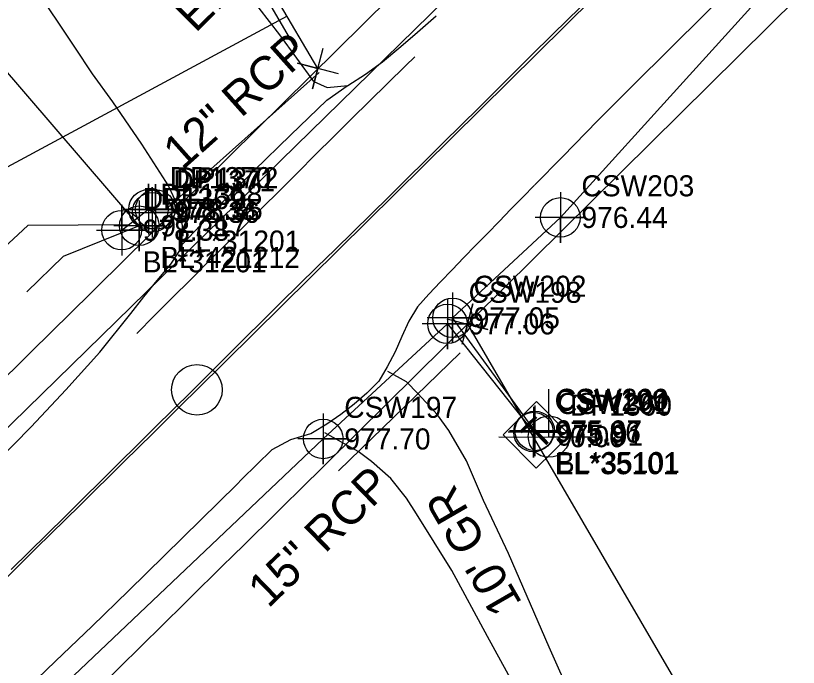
# Model space of a CAD drawing. Extents: x 1182322 to 1186765, y 572295 to 575411.
# Drawn here: x 1185253 to 1185345.8, y 574843 to 574920.3 of the extents above; entities that cross this region are included whole.
import ezdxf

# ---------------------------------------------------------------- set-up
doc = ezdxf.new("R2010")
doc.units = 0
for name, color, linetype in [('COGO Default Chain', 7, 'Continuous'), ('Exist Horizontal Alignment', 7, 'Continuous'), ('Exist Horizontal Alignment Point', 7, 'Continuous'), ('Exist Property Corner CELL', 7, 'Continuous'), ('Exist Property Iron Pin Text', 7, 'Continuous'), ('Exist Property Line', 7, 'Continuous'), ('Exist Property Line Leader', 7, 'Continuous'), ('Exist Right of Way Line', 7, 'Continuous'), ('Exist Roads EOP', 7, 'Continuous'), ('Exist Roads EOP Other', 7, 'Continuous'), ('Exist Roads EOT', 7, 'Continuous'), ('Exist Roads Soil', 7, 'Continuous'), ('Exist Roads Soil Text', 7, 'Continuous'), ('Exist Structure Minor Head and End Wall', 7, 'Continuous'), ('Exist Structure Minor Head and End Wall Cogo Comment', 7, 'Continuous'), ('Exist Structure Minor Head and End Wall Cogo Elevation', 7, 'Continuous'), ('Exist Structure Minor Head and End Wall Cogo Number', 7, 'Continuous'), ('Exist Structure Minor Head and End Wall Cogo Point CELL', 7, 'Continuous'), ('Exist Structure Minor Head and End Wall Leader', 7, 'Continuous'), ('Exist Structure Minor Pipes RCP 12 Inch', 7, 'Continuous'), ('Exist Structure Minor Pipes RCP 12 Inch Cogo Comment', 7, 'Continuous'), ('Exist Structure Minor Pipes RCP 12 Inch Cogo Number', 7, 'Continuous'), ('Exist Structure Minor Pipes RCP 12 Inch Cogo Point CELL', 7, 'Continuous'), ('Exist Structure Minor Pipes RCP 12 Inch Text', 7, 'Continuous'), ('Exist Structure Minor Pipes RCP 15 Inch', 7, 'Continuous'), ('Exist Structure Minor Pipes RCP 15 Inch Text', 7, 'Continuous'), ('Exist Structure Minor Pipes RCP 24 Inch Invert', 7, 'Continuous'), ('Exist Utilities Power Joint Use Telephone CELL', 7, 'Continuous'), ('Exist Utilities Power Joint Use Telephone Cogo Elevation', 7, 'Continuous'), ('Exist Utilities Power Joint Use Telephone Cogo Number', 7, 'Continuous'), ('Exist Utilities Telephone Pedestal CELL', 7, 'Continuous'), ('Exist Utilities Telephone Pedestal Cogo Elevation', 7, 'Continuous'), ('Exist Utilities Telephone Pedestal Cogo Number', 7, 'Continuous'), ('Exist Utilities Telephone UG Cable SUE LOS C', 7, 'Continuous'), ('Exist Utilities Telephone UG Cable SUE LOS C Cogo Comment', 7, 'Continuous'), ('Exist Utilities Telephone UG Cable SUE LOS C Cogo Elevation', 7, 'Continuous'), ('Exist Utilities Telephone UG Cable SUE LOS C Cogo Number', 7, 'Continuous'), ('Exist Utilities Telephone UG Cable SUE LOS C Cogo Point CELL', 7, 'Continuous'), ('Exist Utilities Water UG Line SUE LOS C', 7, 'Continuous')]:
    doc.layers.add(name, color=color, linetype=linetype)

msp = doc.modelspace()

# ---------------------------------------------------------------- linework, layer by layer
at = {"layer": 'COGO Default Chain'}
msp.add_line((1185274.486, 574875.929), (1185408.379, 575008.334), dxfattribs=at)
msp.add_arc((1175733.04, 584524.617), 13569.686, 314.0226276, 314.6798077, dxfattribs=at)
at = {"layer": 'Exist Horizontal Alignment'}
msp.add_line((1185274.486, 574875.929), (1185408.379, 575008.334), dxfattribs=at)
msp.add_arc((1175733.04, 584524.617), 13569.686, 314.0226276, 314.6798077, dxfattribs=at)
at = {"layer": 'Exist Horizontal Alignment Point'}
msp.add_circle((1185274.486, 574875.929), 3, dxfattribs=at)
at = {"layer": 'Exist Property Corner CELL'}
for p, q in [((1185288.832, 574914.024), (1185288.832, 574914.024)), ((1185306.543, 574883.722), (1185306.543, 574883.722))]:
    msp.add_line(p, q, dxfattribs=at)
for points in [[(1185291.252, 574913.394), (1185286.413, 574914.655), (1185288.832, 574914.024), (1185288.202, 574911.605), (1185289.463, 574916.443)], [(1185304.126, 574884.359), (1185308.961, 574883.084), (1185306.543, 574883.722), (1185307.181, 574886.139), (1185305.906, 574881.304)]]:
    msp.add_lwpolyline(points, dxfattribs=at)
at = {"layer": 'Exist Property Line'}
for p, q in [((1185288.832, 574914.024), (1185281.498, 574926.528)), ((1185306.543, 574883.722), (1185478.65, 574588.329))]:
    msp.add_line(p, q, dxfattribs=at)
at = {"layer": 'Exist Property Line Leader'}
msp.add_lwpolyline([(1185285.188, 574920.237), (1185235.405, 574893.412), (1185204.631, 574863.937)], dxfattribs=at)
at = {"layer": 'Exist Right of Way Line'}
for p, q in [((1185262.532, 574888.016), (1185396.426, 575020.422)), ((1185286.439, 574863.841), (1185420.333, 574996.246))]:
    msp.add_line(p, q, dxfattribs=at)
for radius, start in [(13552.686, 314.2300392), (13586.686, 314.1944782)]:
    msp.add_arc((1175733.04, 584524.617), radius, start, 314.6798077, dxfattribs=at)
at = {"layer": 'Exist Roads EOP'}
for points in [[(1185347.529, 574933.236), (1185343.278, 574929.003), (1185339.027, 574924.771), (1185334.768, 574920.546), (1185330.505, 574916.325), (1185326.242, 574912.105), (1185322.008, 574907.855), (1185317.807, 574903.573), (1185314.536, 574900.226)], [(1185288.36, 574912.51), (1185284.33, 574918.038), (1185280.656, 574922.818), (1185277.581, 574926.824)], [(1185288.363, 574912.507), (1185289.911, 574911.777), (1185292.376, 574912.012), (1185294.481, 574913.361), (1185296.497, 574914.837), (1185298.41, 574916.445), (1185300.312, 574918.068), (1185302.2, 574919.706), (1185302.862, 574920.289)], [(1185271.141, 574900.061), (1185270.086, 574901.734), (1185267.967, 574905.07), (1185264.519, 574910.077), (1185262.097, 574913.389)], [(1185272.771, 574893.19), (1185277.037, 574897.696), (1185281.274, 574901.942), (1185285.581, 574906.116), (1185289.899, 574910.281), (1185292.308, 574911.964)], [(1185266.661, 574884.989), (1185268.197, 574886.961), (1185269.785, 574888.89), (1185271.385, 574890.808), (1185272.746, 574892.9), (1185272.774, 574895.397), (1185272.188, 574897.827), (1185271.143, 574900.056)], [(1185314.503, 574900.193), (1185313.106, 574898.763), (1185311.709, 574897.333), (1185310.312, 574895.903), (1185308.914, 574894.473), (1185307.517, 574893.043), (1185306.128, 574891.605), (1185304.743, 574890.163), (1185303.361, 574888.719), (1185301.989, 574887.265), (1185300.646, 574885.784), (1185299.59, 574884.085), (1185298.787, 574882.261), (1185297.975, 574880.437), (1185297.044, 574878.669), (1185296.041, 574876.944), (1185294.627, 574875.529), (1185293.115, 574874.225), (1185291.535, 574873.002), (1185289.899, 574871.857), (1185288.196, 574870.811), (1185287.972, 574870.695)], [(1185224.719, 574842.308), (1185228.998, 574846.513), (1185233.316, 574850.678), (1185237.636, 574854.841), (1185241.957, 574859.003), (1185246.347, 574863.092), (1185250.631, 574867.291), (1185254.856, 574871.549), (1185258.96, 574875.924), (1185262.975, 574880.379), (1185266.642, 574884.965)], [(1185287.952, 574870.689), (1185285.568, 574870.011), (1185283.376, 574868.822), (1185281.598, 574867.065), (1185279.819, 574865.309), (1185279.215, 574864.713)], [(1185279.205, 574864.702), (1185274.932, 574860.49), (1185270.659, 574856.28), (1185266.367, 574852.088), (1185262.073, 574847.9), (1185257.739, 574843.744), (1185253.374, 574839.572), (1185249.07, 574835.458), (1185244.715, 574831.332), (1185240.395, 574827.17), (1185236.11, 574822.972), (1185231.831, 574818.769), (1185227.589, 574814.528), (1185223.349, 574810.285), (1185223.173, 574810.109)]]:
    msp.add_lwpolyline(points, dxfattribs=at)
at = {"layer": 'Exist Roads EOP Other'}
msp.add_lwpolyline([(1185262.097, 574913.389), (1185259.995, 574916.546), (1185250.077, 574931.376), (1185247.899, 574934.733), (1185245.446, 574937.892), (1185242.826, 574940.775), (1185237.847, 574945.524), (1185227.942, 574955.646), (1185217.22, 574966.654), (1185211.604, 574972.127), (1185207.269, 574976.346), (1185195.275, 574987.61), (1185178.895, 575002.931), (1185174.904, 575006.802), (1185172.104, 575009.848), (1185169.088, 575012.685), (1185149.972, 575030.515)], dxfattribs=at)
at = {"layer": 'Exist Roads EOT'}
for points in [[(1185320.734, 574922.076), (1185318.59, 574919.979), (1185316.451, 574917.877), (1185314.32, 574915.766), (1185312.191, 574913.652), (1185310.063, 574911.539), (1185307.934, 574909.426), (1185305.805, 574907.313), (1185303.677, 574905.2), (1185301.548, 574903.087), (1185299.418, 574900.975), (1185297.286, 574898.866), (1185295.147, 574896.763), (1185293.004, 574894.665), (1185290.862, 574892.565), (1185288.721, 574890.465), (1185286.58, 574888.365), (1185284.439, 574886.264), (1185282.302, 574884.16), (1185280.173, 574882.048), (1185278.047, 574879.933), (1185275.92, 574877.818), (1185273.792, 574875.704), (1185271.664, 574873.59), (1185269.536, 574871.476), (1185267.407, 574869.363), (1185265.277, 574867.251), (1185263.147, 574865.14), (1185261.015, 574863.029), (1185258.882, 574860.92), (1185256.748, 574858.813), (1185254.612, 574856.706), (1185252.476, 574854.6)], [(1185267.355, 574882.614), (1185269.477, 574884.734), (1185271.598, 574886.854), (1185273.718, 574888.975), (1185275.839, 574891.096), (1185277.959, 574893.217), (1185280.079, 574895.337), (1185282.2, 574897.458), (1185284.32, 574899.579), (1185286.44, 574901.7), (1185288.56, 574903.821), (1185290.688, 574905.934), (1185292.82, 574908.044), (1185294.951, 574910.155), (1185297.086, 574912.261), (1185299.225, 574914.363), (1185300.303, 574915.421)]]:
    msp.add_lwpolyline(points, dxfattribs=at)
at = {"layer": 'Exist Roads Soil'}
for points in [[(1185286.139, 574916.551), (1185280.456, 574926.323), (1185269.61, 574943.478), (1185250.019, 574976.538), (1185240.669, 574992.978), (1185236.689, 574996.97), (1185233.781, 575000.255), (1185231.347, 575003.099), (1185221.242, 575018.995), (1185207.439, 575010.283), (1185214.604, 574998.816), (1185215.218, 574997.747), (1185215.716, 574996.563), (1185216.433, 574994.858), (1185216.396, 574992.247), (1185215.47, 574988.497)], [(1185351.942, 574746.247), (1185352.472, 574749.736), (1185352.526, 574755.223), (1185351.823, 574762.645), (1185350.856, 574769.332), (1185349.342, 574775.949), (1185347.321, 574782.139), (1185344.159, 574788.72), (1185340.784, 574794.96), (1185335.757, 574804.276), (1185331.021, 574813.582), (1185326.994, 574821.946), (1185321.679, 574833.157), (1185316.254, 574845.408), (1185311.42, 574856.506), (1185308.478, 574862.796), (1185306.425, 574867.519), (1185304.367, 574871.088), (1185303.006, 574872.963), (1185300.672, 574875.507), (1185299.337, 574876.867), (1185297.137, 574878.078)], [(1185345.337, 574753.103), (1185345.588, 574758.315), (1185345.564, 574764.52), (1185344.547, 574771.506), (1185342.41, 574779.004), (1185338.522, 574788.293), (1185332.234, 574800.174), (1185324.951, 574815.353), (1185315.929, 574833.904), (1185308.943, 574846.652), (1185304.696, 574854.48), (1185300.528, 574861.225), (1185299.323, 574863.087), (1185297.465, 574865.42), (1185295.178, 574867.433), (1185293.604, 574868.601), (1185289.66, 574870.831)]]:
    msp.add_lwpolyline(points, dxfattribs=at)
at = {"layer": 'Exist Structure Minor Head and End Wall'}
msp.add_lwpolyline([(1185265.567, 574894.858), (1185268.749, 574897.338), (1185269.185, 574896.974), (1185269.561, 574897.314)], dxfattribs=at)
at = {"layer": 'Exist Structure Minor Head and End Wall Cogo Point CELL'}
for points in [[(1185265.749, 574897.338), (1185271.749, 574897.338), (1185268.749, 574897.338), (1185268.749, 574900.338), (1185268.749, 574894.338)], [(1185266.185, 574896.974), (1185272.185, 574896.974), (1185269.185, 574896.974), (1185269.185, 574899.974), (1185269.185, 574893.974)], [(1185266.561, 574897.314), (1185272.561, 574897.314), (1185269.561, 574897.314), (1185269.561, 574900.314), (1185269.561, 574894.314)], [(1185262.567, 574894.858), (1185268.567, 574894.858), (1185265.567, 574894.858), (1185265.567, 574897.858), (1185265.567, 574891.858)]]:
    msp.add_lwpolyline(points, dxfattribs=at)
for centre in [(1185268.749, 574897.338), (1185269.561, 574897.314), (1185269.185, 574896.974), (1185265.567, 574894.858)]:
    msp.add_circle(centre, 2.344, dxfattribs=at)
at = {"layer": 'Exist Structure Minor Head and End Wall Leader'}
msp.add_lwpolyline([(1185266.371, 574895.484), (1185254.447, 574895.426), (1185251.59, 574892.757)], dxfattribs=at)
at = {"layer": 'Exist Structure Minor Pipes RCP 12 Inch'}
for p, q in [((1185267.651, 574895.382), (1185176.305, 575001.514)), ((1185271.006, 574897.51), (1185288.969, 574913.545))]:
    msp.add_line(p, q, dxfattribs=at)
at = {"layer": 'Exist Structure Minor Pipes RCP 12 Inch Cogo Point CELL'}
msp.add_lwpolyline([(1185267.651, 574898.382), (1185267.651, 574892.382), (1185267.651, 574895.382), (1185270.651, 574895.382), (1185264.651, 574895.382)], dxfattribs=at)
msp.add_circle((1185267.651, 574895.382), 2.344, dxfattribs=at)
at = {"layer": 'Exist Structure Minor Pipes RCP 15 Inch'}
msp.add_line((1185291.29, 574866.325), (1185305.711, 574880.329), dxfattribs=at)
at = {"layer": 'Exist Structure Minor Pipes RCP 24 Inch Invert'}
msp.add_lwpolyline([(1185267.651, 574895.382), (1185258.612, 574891.73), (1185254.327, 574887.529)], dxfattribs=at)
at = {"layer": 'Exist Utilities Power Joint Use Telephone CELL'}
msp.add_line((1185316.218, 574870.365), (1185316.218, 574870.365), dxfattribs=at)
msp.add_lwpolyline([(1185310.28, 574870.365), (1185321.618, 574870.328), (1185316.218, 574870.345), (1185316.218, 574875.99)], dxfattribs=at)
msp.add_circle((1185316.219, 574870.371), 2.45, dxfattribs=at)
at = {"layer": 'Exist Utilities Telephone Pedestal CELL'}
msp.add_line((1185314.665, 574870.553), (1185314.665, 574870.553), dxfattribs=at)
msp.add_lwpolyline([(1185314.716, 574866.628), (1185318.693, 574870.563), (1185314.758, 574874.539), (1185310.781, 574870.605), (1185314.716, 574866.628)], dxfattribs=at)
at = {"layer": 'Exist Utilities Telephone UG Cable SUE LOS C'}
for points in [[(1185314.537, 574871.05), (1185304.789, 574884.458), (1185317.568, 574896.37), (1185348.977, 574931.015), (1185383.664, 574965.193), (1185415.194, 574997.087), (1185448.516, 575030.248)], [(1185174.806, 574734.094), (1185168.685, 574740.67), (1185167.47, 574743.307), (1185170.461, 574748.614), (1185189.397, 574768.113), (1185221.785, 574802.185), (1185254.446, 574836.875), (1185289.46, 574870.098), (1185304.197, 574883.745), (1185314.389, 574870.912)]]:
    msp.add_lwpolyline(points, dxfattribs=at)
at = {"layer": 'Exist Utilities Telephone UG Cable SUE LOS C Cogo Point CELL'}
for points in [[(1185317.568, 574899.37), (1185317.568, 574893.37), (1185317.568, 574896.37), (1185320.568, 574896.37), (1185314.568, 574896.37)], [(1185304.789, 574887.458), (1185304.789, 574881.458), (1185304.789, 574884.458), (1185307.789, 574884.458), (1185301.789, 574884.458)], [(1185304.197, 574886.745), (1185304.197, 574880.745), (1185304.197, 574883.745), (1185307.197, 574883.745), (1185301.197, 574883.745)], [(1185314.389, 574873.912), (1185314.389, 574867.912), (1185314.389, 574870.912), (1185317.389, 574870.912), (1185311.389, 574870.912)], [(1185314.537, 574874.05), (1185314.537, 574868.05), (1185314.537, 574871.05), (1185317.537, 574871.05), (1185311.537, 574871.05)], [(1185289.46, 574873.098), (1185289.46, 574867.098), (1185289.46, 574870.098), (1185292.46, 574870.098), (1185286.46, 574870.098)]]:
    msp.add_lwpolyline(points, dxfattribs=at)
for centre in [(1185317.568, 574896.37), (1185304.789, 574884.458), (1185304.197, 574883.745), (1185314.389, 574870.912), (1185314.537, 574871.05), (1185289.46, 574870.098)]:
    msp.add_circle(centre, 2.344, dxfattribs=at)
at = {"layer": 'Exist Utilities Water UG Line SUE LOS C'}
msp.add_lwpolyline([(1184698.372, 574456.58), (1184835.968, 574463.783), (1185103.91, 574726.55), (1185431.277, 575046.779)], dxfattribs=at)

# ---------------------------------------------------------------- texts
at = {"layer": 'Exist Property Iron Pin Text'}
msp.add_text('EIP', height=4, rotation=44.94755, dxfattribs=at).set_placement((1185274.332, 574918.168))
at = {"layer": 'Exist Roads Soil Text'}
msp.add_text("10' GR", height=4, rotation=120.03147, dxfattribs=at).set_placement((1185313.102, 574850.632))
at = {"layer": 'Exist Structure Minor Head and End Wall Cogo Comment'}
for s, p in [('EL*31201', (1185272.061, 574892.314)), ('BL*31201', (1185268.067, 574889.858))]:
    msp.add_text(s, height=2.5, dxfattribs=at).set_placement(p)
at = {"layer": 'Exist Structure Minor Head and End Wall Cogo Elevation'}
for s, p in [('978.38', (1185271.249, 574896.088)), ('978.35', (1185272.061, 574896.064)), ('978.36', (1185271.685, 574895.724)), ('978.38', (1185268.067, 574893.608))]:
    msp.add_text(s, height=2.5, dxfattribs=at).set_placement(p)
at = {"layer": 'Exist Structure Minor Head and End Wall Cogo Number'}
for s, p in [('DP1370', (1185271.249, 574899.838)), ('DP1372', (1185272.061, 574899.814)), ('DP1371', (1185271.685, 574899.474)), ('DP1369', (1185268.067, 574897.358))]:
    msp.add_text(s, height=2.5, dxfattribs=at).set_placement(p)
at = {"layer": 'Exist Structure Minor Pipes RCP 12 Inch Cogo Comment'}
for s, p in [('977.17', (1185270.151, 574894.132)), ('BL*421212', (1185270.151, 574890.382))]:
    msp.add_text(s, height=2.5, dxfattribs=at).set_placement(p)
at = {"layer": 'Exist Structure Minor Pipes RCP 12 Inch Cogo Number'}
msp.add_text('DP1368', height=2.5, dxfattribs=at).set_placement((1185270.151, 574897.882))
at = {"layer": 'Exist Structure Minor Pipes RCP 12 Inch Text'}
msp.add_text('12" RCP', height=4, rotation=41.75388, dxfattribs=at).set_placement((1185272.752, 574901.884))
at = {"layer": 'Exist Structure Minor Pipes RCP 15 Inch Text'}
msp.add_text('15" RCP', height=4, rotation=44.16094, dxfattribs=at).set_placement((1185282.955, 574849.939))
at = {"layer": 'Exist Utilities Power Joint Use Telephone Cogo Elevation'}
msp.add_text('0.00', height=2.5, dxfattribs=at).set_placement((1185318.718, 574869.115))
at = {"layer": 'Exist Utilities Power Joint Use Telephone Cogo Number'}
msp.add_text('DP1360', height=2.5, dxfattribs=at).set_placement((1185318.718, 574872.865))
at = {"layer": 'Exist Utilities Telephone Pedestal CELL'}
msp.add_text('T', height=3.42, rotation=44.69522, dxfattribs=at).set_placement((1185315.066, 574868.539))
at = {"layer": 'Exist Utilities Telephone Pedestal Cogo Elevation'}
msp.add_text('975.91', height=2.5, dxfattribs=at).set_placement((1185317.165, 574869.303))
at = {"layer": 'Exist Utilities Telephone Pedestal Cogo Number'}
msp.add_text('CSW201', height=2.5, dxfattribs=at).set_placement((1185317.165, 574873.053))
at = {"layer": 'Exist Utilities Telephone UG Cable SUE LOS C Cogo Comment'}
for s, p in [('EL*35101', (1185316.889, 574865.912)), ('BL*35101', (1185317.037, 574866.05))]:
    msp.add_text(s, height=2.5, dxfattribs=at).set_placement(p)
at = {"layer": 'Exist Utilities Telephone UG Cable SUE LOS C Cogo Elevation'}
for s, p in [('976.44', (1185320.068, 574895.12)), ('977.05', (1185307.289, 574883.208)), ('977.06', (1185306.697, 574882.495)), ('975.96', (1185316.889, 574869.662)), ('975.97', (1185317.037, 574869.8)), ('977.70', (1185291.96, 574868.848))]:
    msp.add_text(s, height=2.5, dxfattribs=at).set_placement(p)
at = {"layer": 'Exist Utilities Telephone UG Cable SUE LOS C Cogo Number'}
for s, p in [('CSW203', (1185320.068, 574898.87)), ('CSW202', (1185307.289, 574886.958)), ('CSW198', (1185306.697, 574886.245)), ('CSW199', (1185316.889, 574873.412)), ('CSW200', (1185317.037, 574873.55)), ('CSW197', (1185291.96, 574872.598))]:
    msp.add_text(s, height=2.5, dxfattribs=at).set_placement(p)

doc.saveas('drawing.dxf')
